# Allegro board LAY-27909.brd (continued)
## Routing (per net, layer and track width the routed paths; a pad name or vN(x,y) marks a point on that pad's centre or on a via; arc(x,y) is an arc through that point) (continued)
LSENSE_EMITTER: length 5
  TOP w0.127: R58.1 72.93,7.28 73.2,7.01 Q2.2 72.6,5.86 72.6,5.86 C39.1 72.03,5.2 72.03,5.2 R59.1
Net_129: length 3.6
  TOP w0.127: v1(65.87,12.47) 62.23,12.47
Net_151: length 2.8
  TOP w0.127: v1(41.57,11.81) 44.33,11.81
Net_152: length 3.6
  TOP w0.127: 46.88,12.31 v1(50.49,12.31)
Net_157: length 2.9
  TOP w0.127: 54.36,30.29 54.36,30.82 54.36,32.22 54.69,32.55 v1(54.69,33.02)
RGPIO3_MMA9553L: length 2.5
  TOP w0.127: R51.2 33.08,10.34 33.66,10.34 33.86,10.54 33.86,11.2 34.05,11.39 U11.8
RST_ACCEL: length 5.5
  TOP w0.127: R46.2 50.27,13.79 R47.1 50.26,13.43 v1(49.64,12.81) U10.16
RST_BT: length 7.5
  TOP w0.127: C46.1 R2.1 73.04,33.53 73.05,33.54 SW5.1 73.99,32.8 73.83,32.64 72.42,32.64 72.15,32.37 U5.3
RST_FXAS21000CQ: length 3.4
  TOP w0.127: R28.1 R27.2 21.05,23.85 21.42,24.22 U4.4
RST_FXOS8700CQ: length 6.1
  TOP w0.127: U9.16 v1(64.99,12.97) R44.1 R45.1
RST_MMA9553L: length 3.1
  TOP w0.127: U11.3 36.12,13.79 36.24,13.91 R42.2 36.25,14.83 R41.2
RST_TGTMCU: length 78.4
  TOP w0.127: v1(44.02,17.25) 43.59,16.81 R35.2 42.27,16.81 42.26,16.82 U6.4 ; v1(49.91,16.43) 51.27,16.43 51.76,15.95 R46.1 51.88,15.31 52.88,14.31 52.88,12.24 50.9,10.26 50.9,5.36 51.97,4.29 59.41,4.29 61.37,6.25 64.26,6.25 67.87,9.86 67.87,11.26 68.22,11.61 R44.2 68.24,12.98 v1(69.14,12.98) ; R2.2 v1(68.4,33.53)
  BOTTOM w0.127: v1(44.02,17.25) 44.02,17.27 44.53,17.78 47.68,17.78 48.29,17.17 49.17,17.17 v1(49.91,16.43) ; v1(68.4,33.53) 64.74,33.53 62.66,31.45 62.66,20.02 63.63,19.05 65.79,19.05 69.14,15.7 v1(69.14,12.98)
RST_TGTMCU_B: length 41.2
  TOP w0.127: R28.2 24.41,22.85 24.83,23.27 27.34,23.27 28.43,24.37 32.45,24.37 v1(32.94,23.88) ; R41.1 v1(37.75,17.35) 38.2,17.35 38.33,17.48 U6.2
  BOTTOM w0.127: J9.3 32.98,4.23 34.32,5.56 38.13,5.56 39.5,6.93 39.5,15.61 v1(37.75,17.35) 37.15,17.95 37.15,19.67 v1(32.94,23.88)
SA0_FXOS8700CQ: length 6.9
  TOP w0.127: U9.10 60.45,8.09 60.03,7.67 R57.2 59.04,6.91 59.05,6.9 J23.2
SA1_FXOS8700CQ: length 12.5
  TOP w0.127: R55.2 54.69,8.43 53.83,9.29 J21.1 52.52,10.58 54.4,12.47 v2(56.07,12.47) U9.7
SA_GYRO: length 6.2
  TOP w0.127: U4.13 23.27,28.54 23.74,29.01 R5.2 25.67,30.52 26.23,31.08 J8.2
SD_CARD_DETECT: length 9.7
  TOP w0.127: J11.G1 1.78,27.74 1.57,27.94 1.57,34.09 TP22.1
SD_CLK: length 9.4
  TOP w0.127: R9.2 8.66,30.12 7.03,28.49 J11.P5
SD_CMD: length 9.9
  TOP w0.127: R22.2 9.6,23.47 6.78,26.29 J11.P3
SD_DAT0: length 9.6
  TOP w0.127: J11.P7 6.71,30.69 7.67,31.65 9.73,31.65 11.02,32.94 R3.2
SD_DAT1: length 7.6
  TOP w0.127: TP23.1 6.27,34.9 6.27,32.99 5.07,31.79 J11.P8
SD_DAT2: length 5
  TOP w0.127: TP24.1 2.48,20.46 J11.P1
SD_DAT3: length 12.8
  TOP w0.127: R1.2 9.35,18.69 8.61,19.43 TP21.1 6.45,20.37 6.45,23.8 5.06,25.19 J11.P2
SNS_LIGHT: length 14.3
  TOP w0.127: R58.2 69.88,7.28 69.57,7.59 TP29.1 66.57,7.59 64.31,5.33 61.21,5.33 J10.4
SPI_CLK: length 81.8
  TOP w0.127: R9.1 12.27,31.65 v1(12.29,31.62) 12.29,33.15 13.87,34.72 21.67,34.72 22.69,35.75 22.69,37.12 23.53,37.95 26.32,37.95 TP12.1 ; v1(35.56,19.63) 39.66,19.63 40.33,18.97 40.33,16.57 40.72,16.17 43.61,16.17 44.66,17.22 v1(45.1,17.22) U10.4
  BOTTOM w0.127: J2.6 30.3,49.56 30.3,41.94 TP12.1 ; v1(35.56,19.63) 35.11,19.63 35.08,19.6 26.71,19.6 25.59,20.73 18.85,20.73 18.11,21.46 18.11,25.36 12.29,31.18 v1(12.29,31.62)
SPI_MISO: length 83.6
  TOP w0.127: v1(26.72,39.01) 23.44,39.01 22.15,37.72 22.15,36.17 21.41,35.43 13.16,35.43 v1(12.19,34.47) R3.1 ; U10.7 v2(40.72,12.31) 40.72,12.8 40.84,12.93 40.84,15.28 39.78,16.34 39.78,18.61 39.37,19.02 35.16,19.02 34.66,19.52 34.66,19.9 v1(34.35,20.22)
  BOTTOM w0.127: v1(26.72,39.01) 29.92,39.01 TP13.1 32.82,41.91 32.82,49.58 J2.5 ; v1(34.35,20.22) 34.04,20.53 26.36,20.53 25.78,21.11 19.18,21.11 18.44,21.84 18.44,28.22 v1(12.19,34.47)
SPI_MOSI: length 84.8
  TOP w0.127: U10.6 v2(41.57,12.81) ; TP14.1 30.91,37.46 26.26,37.46 25.22,36.42 25.22,35.18 23.95,33.91 15.11,33.91 14.27,33.07 14.27,27 v1(12.27,24.99) R22.1 ; v1(38,18.06) 37.59,18.47 v1(35.66,18.47)
  BOTTOM w0.127: v2(41.57,12.81) 41.57,14.49 v1(38,18.06) ; v1(35.66,18.47) 35.15,18.97 25.92,18.97 24.65,20.24 18.69,20.24 17.75,21.18 17.75,24.26 17.02,24.99 v1(12.27,24.99) ; TP14.1 35.38,41.94 35.38,49.56 J2.4
SPI_SS_SD: length 53.9
  TOP w0.127: R1.1 9.35,15.39 v1(9.7,15.04) ; J10.3 54.71,3.78 45.47,3.78 TP35.1 42.01,7.24 42.01,7.26 38.27,7.26 36.56,5.56 34.35,5.56 32.79,7.12 24.85,7.12 24.85,7.12 v1(24.21,7.12)
  BOTTOM w0.127: v1(9.7,15.04) 16.29,15.04 v1(24.21,7.12)
SPI_SS_SPI_ACCEL: length 52.1
  TOP w0.127: U10.10 v1(45.1,7.32)
  BOTTOM w0.127: v1(45.1,7.32) 44.6,7.32 43.79,8.13 43.79,15.16 41.38,17.58 41.38,25.83 39.95,27.25 39.95,37.36 TP15.1 37.92,41.94 37.92,49.56 J2.3
TP_FRDM_DIG03: length 11.3
  BOTTOM w0.127: J1.4 54.64,49.61 54.64,41.94 TP5.1
TP_FRDM_DIG06: length 11.3
  BOTTOM w0.127: TP2.1 47.02,41.94 47.02,49.61 J1.7
TP_FRDM_DIG07: length 11.3
  BOTTOM w0.127: TP1.1 44.48,41.94 44.48,49.61 J1.8
TP_FRDM_DIG09: length 11.2
  BOTTOM w0.127: J2.2 40.46,49.56 40.46,41.94 TP16.1
VREGD_FXAS21000CQ: length 1.8
  TOP w0.127: C8.1 21.18,29.43 21.42,29.19 U4.16

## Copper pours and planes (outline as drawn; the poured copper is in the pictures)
GND on TOP: 0.53,40.64 4.1,49.24 12.7,52.81 68.58,52.81 77.18,49.24 80.75,40.64 80.75,12.7 77.18,4.1 68.58,0.53 12.73,0.53 4.11,4.1 0.53,12.7 ; 25 cut-outs
GND on BOTTOM: 0.53,40.64 4.1,49.24 12.7,52.81 68.58,52.81 77.18,49.24 80.75,40.64 80.75,12.7 77.18,4.1 68.58,0.53 12.73,0.53 4.11,4.1 0.53,12.7 ; 25 cut-outs

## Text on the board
BOTTOM: 170-27909 REV C | 2 OF 8 | SECONDARY SIDE
Ref Des/Assembly Bottom: D13 | D8
Board Geometry/Soldermask Bottom: 6 OF 8 | SECONDARY SOLDERMASK
Ref Des/Silkscreen Bottom: D15 | D14 | AREF | GND | D13 | D12 | D11 | D10 | D9 | D8 | D7 | D6 | D5 | D4 | D3 | D2 | D1 | D0 | A0 | A5 | SD_DET | SD_DAT2 | SD_DAT1 | SD_DAT3 | BAT PWR | 3V3_PEDOM | 3V3_BAT | 1V8_PEDOM | POWER | BT_MONITOR | 700-XXXXX | SCH-XXXXX | SNS_LIGHT | BT_WAKEUP | 2 | BAT | OFF/CHARGE | GYRO | I2C_SCL0 | ON | I2C_SDA0 | SPI_CLK | SPI_MISO | SPI_MOSI | PRESSURE | SPI_SS_ACCEL | TP_FRDM_DIG09 | ACCEL | INT_PED | TP_FRDM_DIG07 | SPI_ACC | TP_FRDM_DIG06 | INT_GYRO | INT_ACCEL | MAG | TP_FRDM_DIG03 | SPI_SS_DD | INT_MAG1 | COMBO | BT_TX0 | I2C_SDA1 | BT_RX0 | I2C_SCL1 | 8 OF 8 | SECONDARY SILKSCREEN
User.Comments: 1 OF 1 | TEST PROBE | 1/1 | 1
TOP: 1 OF 8 | PRIMARY SIDE
Board Geometry/Soldermask Top: 3 OF 8 | PRIMARY SOLDERMASK
Ref Des/Silkscreen Top: OFF | Y | GYRO | Z | ON | R16 | PRES | PEDOM | ACCEL | SCL1 | SDA1 | R12 | X | MAG | TX | RX | COMBO | R57 | R45 | LIGHT | BLUETOOTH | uSD CARD | GND | C8 | C21 | R6 | SPI_ACCEL | 1 | 5 OF 8 | FRDM-FXS-MULTI | PRIMARY SILKSCREEN | REV C
DIMENSION: PRIMARY | SIDE | SECONDARY | GRID ORIGIN | PRIMARY DATUM
BODY_CENTER: 23. DO NOT PROVIDE SOLDERMASK CLEARANCES FOR THE SPECIFIC LOCATIONS | 22. | LEAVE SOLDERMASK AS THEY APPEAR ON CAD. | INTENTIONAL SHORT ON J12 BETWEEN NETS P3V3 AND P3V3_MAG | INTENTIONAL SHORT ON J20 BETWEEN NETS P1V8 AND P1V8_PED | INTENTIONAL SHORT ON J17 BETWEEN NETS P3V3 AND P3V3_SPI_ACC | INTENTIONAL SHORT ON J18 BETWEEN NETS P3V3_PEDOM AND P3V3 | INTENTIONAL SHORT ON J8 BETWEEN NETS GND AND SA_GYRO | INTENTIONAL SHORT ON J21 BETWEEN NETS GND AND SA1_FXOS8700CQ | INTENTIONAL SHORT ON J23 BETWEEN NETS GND AND SA0_FXOS8700CQ | INTENTIONAL SHORT ON J25 BETWEEN NETS BT_RX0 AND BT_TX | INTENTIONAL SHORT ON J26 BETWEEN NETS BT_TX0 AND BT_RX | INTENTIONAL SHORT ON J16 BETWEEN NETS P3V3 AND P3V3_COMBO | INTENTIONAL SHORT ON J19 BETWEEN NETS P4V2_BAT_OUT AND P4V2_BAT | INTENTIONAL SHORT ON J13 BETWEEN NETS P3V3 AND P3V3_ACCEL | INTENTIONAL SHORT ON J14 BETWEEN NETS P3V3 AND P3V3_PRESSURE | INTENTIONAL SHORT ON J15 BETWEEN NETS P3V3 AND  P3V3_GYRO | 17 | 16 | 23 | 8
PASTEMASK_TOP: 4 OF 8 | PASTEMASK TOP
User.5: 7 OF 8 | SECONDARY PASTEMASK
User.15: 10-25-13 | 09-27-13 | 08-28-13 | 11-21-13 | R.D.R | C1 | C | B | C2 | ECO46962 / FAB NOTE CORRECTION | RE-SPIN PER ECO46387 | RE-SPIN PER ECO45632 | BOARD ORIGIN CORRECTED
User.19: FIGURE | SIZE | 10.0 | 12.0 | 35.0 | 40.0 | 41.0 | 28.0 | DRILL CHART: TOP to BOTTOM | ALL UNITS ARE IN MILS | TOLERANCE | +0.0/-10.0 | +2.0/-2.0 | +3.0/-3.0 | PLATED | NON-PLATED | QTY | 457 | 16 | 115 | 6 | 84 | 2
